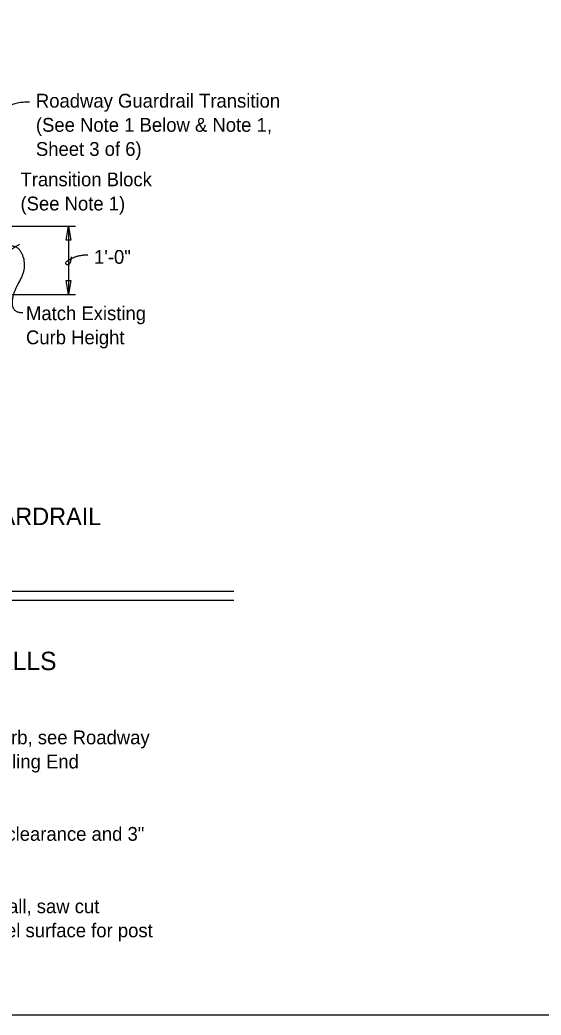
# Model space of a CAD drawing. Extents: x 1.5 to 68.7, y 0 to 31.
# Drawn here: x 12.85 to 20.46, y 1.78 to 16.3 of the extents above; entities that cross this region are included whole.
import ezdxf

# ---------------------------------------------------------------- set-up
doc = ezdxf.new("R2010")
doc.units = 0
for name, color, linetype in [('ActivePts-ConstElements', 7, 'Continuous'), ('AdhocPoint_dp', 7, 'Continuous'), ('TextMisc', 7, 'Continuous')]:
    doc.layers.add(name, color=color, linetype=linetype)

# ---------------------------------------------------------------- blocks, each defined once
blk = doc.blocks.new('Terminator-Arrow')
at = {"layer": 'AdhocPoint_dp'}
blk.add_lwpolyline([(0, 0), (-0.00041, 0.000069), (-0.00041, -0.000069)], close=True, dxfattribs=at)

msp = doc.modelspace()

# ---------------------------------------------------------------- linework, layer by layer
at = {"layer": 'ActivePts-ConstElements'}
msp.add_lwpolyline([(1.467, 28.183), (42.533, 28.183), (42.533, 1.783), (1.467, 1.783)], close=True, dxfattribs=at)
at = {"layer": 'AdhocPoint_dp'}
for p, q in [((10.687, 13.296), (13.662, 13.296)), ((13.562, 13.296), (13.562, 12.296)), ((10.687, 12.296), (13.662, 12.296)), ((11.614, 7.968), (15.974, 7.968)), ((11.614, 7.835), (15.974, 7.835))]:
    msp.add_line(p, q, dxfattribs=at)
for points in [[(12.992, 15.103), (12.706, 15.112), (12.429, 14.783), (12.063, 14.685), (11.893, 14.586)], [(12.894, 12.029), (12.743, 12.029), (12.743, 12.31), (12.921, 12.612), (12.921, 12.831), (12.818, 13.003), (12.647, 13.003), (12.571, 12.921), (12.674, 12.921), (12.846, 13.03)], [(13.603, 12.849), (13.587, 12.708), (13.486, 12.76), (13.703, 12.877), (13.845, 12.877)]]:
    msp.add_open_spline(points, degree=2, dxfattribs=at)

# ---------------------------------------------------------------- block references
at = {"layer": 'AdhocPoint_dp', "xscale": 506.349, "yscale": -512.1577380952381}
for p, rotation in [((13.561, 13.296), 90), ((13.561, 12.296), -90)]:
    msp.add_blockref('Terminator-Arrow', p, dxfattribs=dict(at, rotation=rotation))

# ---------------------------------------------------------------- texts
at = {"layer": 'AdhocPoint_dp'}
for s, height, p in [('Roadway Guardrail Transition', 0.2016, (13.086, 15.024)), ('(See Note 1 Below & Note 1,', 0.2016, (13.086, 14.672)), ('Sheet 3 of 6)', 0.2016, (13.086, 14.32)), ('Transition Block', 0.2016, (12.861, 13.876)), ('(See Note 1)', 0.2016, (12.861, 13.524)), ('Match Existing ', 0.2016, (12.941, 11.923)), ('Curb Height', 0.2016, (12.941, 11.571)), ('PARTIAL ELEVATION OF INSIDE FACE OF GUARDRAIL', 0.256, (5.119, 8.932)), ('PERPENDICULAR OR ANGLED WING WALLS', 0.2688, (5.717, 6.816)), ('1. Provide Transition Block (as shown) or Curb if existing Approach Slab does not have a curb, see Roadway ', 0.2016, (1.755, 5.734)), ('   Plans.  Shape and height of Transition Block or Curb shall match existing bridge curb.  Railing End ', 0.2016, (1.755, 5.382)), ('2. Field bend Dowel Bars 4L within Transition Block as required to maintain 2" top and side clearance and 3" ', 0.2016, (1.755, 4.326)), ('3. If a Special Steel Guardrail Post is required for attachment to the top of a sloping Wing Wall, saw cut ', 0.2016, (1.755, 3.27)), ('   and remove a wedge shaped portion of the sloping Wing Wall as required to provide a level surface for post', 0.2016, (1.755, 2.918))]:
    msp.add_text(s, height=height, dxfattribs=at).set_placement(p)
at = {"layer": 'TextMisc'}
msp.add_text('1\'-0"', height=0.2016, dxfattribs=at).set_placement((13.935, 12.745))

doc.saveas('drawing.dxf')
